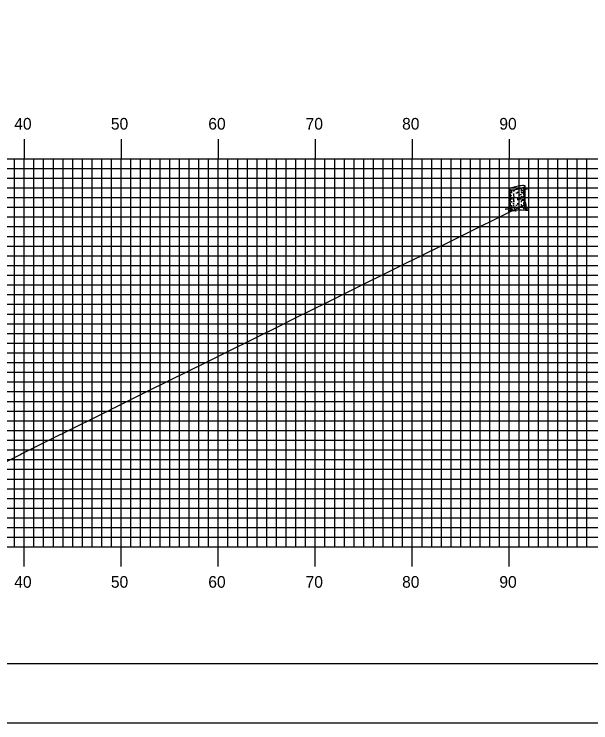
# Model space of a CAD drawing. Extents: x 1684799 to 1685142, y 461260 to 461480.
# Drawn here: x 1685003.7 to 1685063.1, y 461260 to 461333 of the extents above; entities that cross this region are included whole.
import ezdxf

# ---------------------------------------------------------------- set-up
doc = ezdxf.new("R2010")
doc.units = 0
for name, color, linetype in [('BORDER', 7, 'Continuous'), ('H_V ANNOTATION', 7, 'Continuous'), ('M_Trees_Conifer_Pay', 7, 'Continuous'), ('MAJOR', 7, 'Continuous'), ('MINOR', 7, 'Continuous'), ('PLOT BOUNDARY', 7, 'Continuous'), ('S_Roadway_Centerline', 7, 'Continuous')]:
    doc.layers.add(name, color=color, linetype=linetype)

msp = doc.modelspace()

# ---------------------------------------------------------------- linework, layer by layer
at = {"layer": 'BORDER'}
msp.add_lwpolyline([(1684815.116, 461266.072), (1685135.116, 461266.072), (1685135.116, 461476.072), (1684815.116, 461476.072)], close=True, dxfattribs=at)
at = {"layer": 'M_Trees_Conifer_Pay'}
for p, q in [((1685054.699, 461313.193), (1685054.699, 461314.915)), ((1685054.746, 461314.878), (1685054.746, 461314.406)), ((1685054.805, 461314.866), (1685054.805, 461314.769)), ((1685054.93, 461314.858), (1685054.93, 461314.626)), ((1685055.15, 461314.879), (1685055.15, 461314.711)), ((1685055.946, 461314.921), (1685055.946, 461314.721)), ((1685056.174, 461315.117), (1685056.174, 461314.894)), ((1685056.174, 461314.805), (1685056.174, 461314.758)), ((1685056.291, 461315.178), (1685056.291, 461315.015)), ((1685056.291, 461314.948), (1685056.291, 461314.82)), ((1685056.363, 461313.603), (1685056.363, 461315.25)), ((1685054.746, 461314.342), (1685054.746, 461314.034)), ((1685054.805, 461314.694), (1685054.805, 461314.49)), ((1685054.805, 461314.433), (1685054.805, 461314.233)), ((1685054.805, 461314.186), (1685054.805, 461313.85)), ((1685054.93, 461314.586), (1685054.93, 461314.511)), ((1685054.93, 461314.108), (1685054.93, 461313.969)), ((1685055.15, 461314.474), (1685055.15, 461314.237)), ((1685055.555, 461314.647), (1685055.555, 461314.552)), ((1685055.946, 461314.664), (1685055.946, 461314.575)), ((1685055.946, 461314.227), (1685055.946, 461314.122)), ((1685056.174, 461314.423), (1685056.174, 461314.291)), ((1685056.174, 461314.18), (1685056.174, 461314.07)), ((1685056.231, 461314.622), (1685056.18, 461314.563)), ((1685056.291, 461314.633), (1685056.291, 461314.297)), ((1685056.291, 461314.26), (1685056.291, 461314.097)), ((1685054.746, 461313.986), (1685054.746, 461313.494)), ((1685054.746, 461313.441), (1685054.746, 461313.193)), ((1685054.805, 461313.797), (1685054.805, 461313.661)), ((1685054.805, 461313.562), (1685054.805, 461313.183)), ((1685054.93, 461313.698), (1685054.93, 461313.556)), ((1685055.15, 461313.992), (1685055.15, 461313.84)), ((1685055.15, 461313.797), (1685055.15, 461313.624)), ((1685055.15, 461313.346), (1685055.15, 461313.193)), ((1685055.555, 461314.034), (1685055.555, 461313.96)), ((1685055.555, 461313.935), (1685055.555, 461313.786)), ((1685055.555, 461313.494), (1685055.555, 461313.341)), ((1685055.946, 461313.755), (1685055.946, 461313.609)), ((1685055.946, 461313.377), (1685055.946, 461313.288)), ((1685056.174, 461313.935), (1685056.174, 461313.793)), ((1685056.174, 461313.566), (1685056.174, 461313.393)), ((1685056.291, 461314.05), (1685056.291, 461313.834)), ((1685056.291, 461313.803), (1685056.291, 461313.729)), ((1685056.291, 461313.688), (1685056.291, 461313.515)), ((1685054.93, 461313.294), (1685054.93, 461313.2)), ((1685054.93, 461312.8), (1685055.093, 461312.864)), ((1685055.367, 461312.736), (1685055.241, 461312.8))]:
    msp.add_line(p, q, dxfattribs=at)
for points in [[(1685056.18, 461314.748), (1685056.217, 461314.674), (1685056.264, 461314.731), (1685056.322, 461314.799), (1685056.414, 461314.993), (1685056.478, 461315.04), (1685056.509, 461315.047)], [(1685056.194, 461314.495), (1685056.231, 461314.622), (1685056.295, 461314.738), (1685056.326, 461314.805), (1685056.394, 461314.952)], [(1685056.409, 461314.981), (1685056.484, 461314.989), (1685056.556, 461314.89)], [(1685054.878, 461314.221), (1685054.872, 461314.316), (1685054.915, 461314.293), (1685054.915, 461314.198)], [(1685056.146, 461314.711), (1685056.116, 461314.626), (1685056.112, 461314.559), (1685056.142, 461314.495)], [(1685056.363, 461313.603), (1685056.414, 461313.341), (1685056.43, 461313.068), (1685056.488, 461312.942), (1685056.624, 461312.912), (1685056.394, 461312.874), (1685056.394, 461312.874), (1685056.4, 461312.827), (1685056.647, 461312.733), (1685056.373, 461312.749), (1685056.017, 461312.769), (1685055.696, 461312.759), (1685055.702, 461312.841), (1685055.554, 461312.759), (1685055.367, 461312.736), (1685055.391, 461312.668), (1685055.123, 461312.712), (1685054.903, 461312.685), (1685054.61, 461312.702), (1685054.899, 461312.759), (1685054.93, 461312.8), (1685054.767, 461312.858), (1685054.53, 461312.868), (1685054.289, 461312.868), (1685054.631, 461312.926), (1685054.673, 461313.006), (1685054.699, 461313.193)], [(1685056.017, 461313.822), (1685056.03, 461313.745), (1685056.077, 461313.755), (1685056.064, 461313.922)], [(1685056.289, 461313.461), (1685056.295, 461313.315), (1685056.342, 461313.247), (1685056.352, 461313.047)], [(1685054.747, 461313.146), (1685054.726, 461313.068), (1685054.705, 461312.973)], [(1685054.825, 461313.126), (1685054.831, 461313.01), (1685054.778, 461312.921), (1685054.767, 461312.858)], [(1685054.988, 461313.152), (1685054.988, 461313.021), (1685054.899, 461312.921)], [(1685055.214, 461312.912), (1685055.282, 461313.006), (1685055.308, 461313.146)], [(1685055.702, 461312.841), (1685055.776, 461312.983), (1685055.786, 461313.084)], [(1685055.953, 461313.21), (1685055.963, 461313.084), (1685056.037, 461313.041)], [(1685056.231, 461312.821), (1685056.217, 461312.959), (1685056.142, 461313.088)], [(1685056.19, 461313.315), (1685056.264, 461313.21), (1685056.268, 461313.037), (1685056.394, 461312.874)]]:
    msp.add_lwpolyline(points, dxfattribs=at)
for centre, radius, start, end in [((1685054.73, 461314.914), 0.0314, 156.51582, 169.2194), ((1685054.725, 461314.915), 0.0264, 169.2194, 180.03145), ((1685054.722, 461314.915), 0.0226, 180.03145, 191.7194), ((1685054.722, 461314.915), 0.0226, 191.7194, 203.40735), ((1685054.75, 461314.905), 0.0527, 146.7194, 156.51582), ((1685054.725, 461314.916), 0.0264, 203.40735, 214.2194), ((1685054.729, 461314.919), 0.0314, 214.2194, 226.92298), ((1685054.774, 461314.889), 0.0817, 132.38868, 146.7194), ((1685054.744, 461314.935), 0.0527, 226.92298, 236.7194), ((1685054.76, 461314.959), 0.0817, 236.7194, 251.05013), ((1685054.888, 461314.765), 0.251, 124.2194, 132.38868), ((1685054.815, 461315.118), 0.251, 251.05013, 259.2194), ((1685055.198, 461314.309), 0.802, 108.05939, 124.2194), ((1685054.918, 461315.66), 0.802, 259.2194, 275.37941), ((1685056.555, 461310.147), 5.179, 101.7194, 108.05939), ((1685054.507, 461320.018), 5.179, 275.37941, 281.7194), ((1685055.531, 461318.927), 4.124, 264.6955, 266.73309), ((1685056.555, 461310.147), 5.179, 95.37941, 101.7194), ((1685054.507, 461320.018), 5.179, 281.7194, 288.05939), ((1685055.531, 461318.927), 4.124, 276.23804, 278.1032), ((1685056.144, 461314.505), 0.802, 79.2194, 95.37941), ((1685056.032, 461315.409), 0.571, 278.1032, 284.36665), ((1685055.864, 461315.856), 0.802, 288.05939, 304.2194), ((1685056.032, 461315.564), 0.571, 284.43166, 292.41325), ((1685056.032, 461315.409), 0.571, 297.0237, 300), ((1685056.247, 461315.047), 0.251, 71.05013, 79.2194), ((1685056.174, 461315.4), 0.251, 304.2194, 312.38868), ((1685056.231, 461315.219), 0.172, 300, 311.25059), ((1685056.231, 461315.064), 0.172, 300, 311.25059), ((1685056.302, 461315.206), 0.0817, 56.7194, 71.05013), ((1685056.288, 461315.276), 0.0817, 312.38868, 326.7194), ((1685056.304, 461315.136), 0.0624, 311.25059, 330), ((1685056.304, 461314.982), 0.0624, 311.25059, 330), ((1685056.318, 461315.231), 0.0527, 46.92298, 56.7194), ((1685056.333, 461315.246), 0.0314, 34.2194, 46.92298), ((1685056.312, 461315.26), 0.0527, 326.7194, 336.51582), ((1685056.319, 461315.127), 0.0441, 330, 343.94846), ((1685056.319, 461314.973), 0.0441, 330, 343.94846), ((1685056.337, 461315.249), 0.0264, 23.40735, 34.2194), ((1685056.332, 461315.251), 0.0314, 336.51582, 349.2194), ((1685056.34, 461315.25), 0.0226, 11.7194, 23.40735), ((1685056.33, 461315.124), 0.0334, 343.94846, 354.21506), ((1685056.33, 461314.97), 0.0334, 343.94846, 354.21506), ((1685056.34, 461315.25), 0.0226, 0.03145, 11.7194), ((1685056.337, 461315.25), 0.0264, 349.2194, 0.03145), ((1685054.731, 461314.737), 0.0334, 163.94846, 180), ((1685054.731, 461314.737), 0.0334, 180, 196.05154), ((1685054.731, 461314.29), 0.0334, 163.94846, 180), ((1685054.731, 461314.29), 0.0334, 180, 196.05154), ((1685054.731, 461314.08), 0.0334, 163.94846, 180), ((1685054.731, 461314.08), 0.0334, 180, 196.05154), ((1685054.741, 461314.74), 0.0441, 196.05154, 210), ((1685054.741, 461314.293), 0.0441, 196.05154, 210), ((1685054.757, 461314.749), 0.0624, 210, 228.74941), ((1685054.757, 461314.302), 0.0624, 210, 228.74941), ((1685054.83, 461314.831), 0.172, 228.74941, 240), ((1685054.83, 461314.385), 0.172, 228.74941, 240), ((1685055.029, 461315.176), 0.571, 240, 240.33672), ((1685055.029, 461314.73), 0.571, 240, 240.33672), ((1685055.03, 461314.965), 0.571, 240, 247.05866), ((1685055.029, 461315.176), 0.571, 246.85973, 257.98457), ((1685055.53, 461318.247), 4.124, 264.08098, 266.66759), ((1685055.53, 461318.694), 4.124, 268.07512, 270), ((1685055.53, 461318.694), 4.124, 270, 270.35814), ((1685055.531, 461318.483), 4.124, 273.70524, 275.95043), ((1685055.53, 461318.694), 4.124, 275.78493, 277.05584), ((1685055.53, 461318.247), 4.124, 277.61247, 278.1032), ((1685056.031, 461314.73), 0.571, 278.1032, 286.92962), ((1685056.032, 461314.965), 0.571, 284.44928, 297.04285), ((1685056.031, 461314.73), 0.571, 297.18959, 300), ((1685056.23, 461314.385), 0.172, 300, 311.25059), ((1685056.302, 461314.302), 0.0624, 311.25059, 330), ((1685056.318, 461314.293), 0.0441, 330, 343.94846), ((1685056.328, 461314.29), 0.0334, 343.94846, 354.21506), ((1685056.328, 461314.08), 0.0334, 343.94846, 354.21506), ((1685056.33, 461314.526), 0.0334, 343.94846, 354.21506), ((1685054.731, 461313.843), 0.0334, 163.94846, 180), ((1685054.731, 461313.843), 0.0334, 180, 196.05154), ((1685054.731, 461313.645), 0.0334, 163.94846, 180), ((1685054.731, 461313.45), 0.0334, 163.94846, 180), ((1685054.731, 461313.45), 0.0334, 180, 196.05154), ((1685054.741, 461314.083), 0.0441, 196.05154, 210), ((1685054.741, 461313.846), 0.0441, 196.05154, 210), ((1685054.741, 461313.453), 0.0441, 196.05154, 210), ((1685054.757, 461314.092), 0.0624, 210, 228.74941), ((1685054.757, 461313.855), 0.0624, 210, 228.74941), ((1685054.757, 461313.462), 0.0624, 210, 228.74941), ((1685054.83, 461314.175), 0.172, 228.74941, 240), ((1685054.83, 461313.938), 0.172, 228.74941, 240), ((1685054.83, 461313.545), 0.172, 228.74941, 240), ((1685055.029, 461314.52), 0.571, 240, 246.85973), ((1685055.029, 461314.283), 0.571, 240, 246.85973), ((1685055.018, 461314.091), 0.571, 241.23686, 248.02677), ((1685055.029, 461313.89), 0.571, 240, 246.85973), ((1685055.029, 461314.52), 0.571, 259.27072, 261.8968), ((1685055.53, 461318.037), 4.124, 261.8968, 263.14738), ((1685055.53, 461317.603), 4.124, 263.49906, 265.83975), ((1685055.53, 461317.8), 4.124, 264.71603, 266.31934), ((1685055.53, 461318.037), 4.124, 270, 270.35814), ((1685055.53, 461318.037), 4.124, 273.14934, 275.45691), ((1685056.031, 461314.283), 0.571, 285.39827, 297.18959), ((1685056.031, 461313.89), 0.571, 288.50673, 297.27208), ((1685056.031, 461314.085), 0.571, 289.29072, 300), ((1685056.031, 461314.52), 0.571, 297.18959, 300), ((1685056.23, 461314.175), 0.172, 300, 311.25059), ((1685056.23, 461313.74), 0.172, 300, 311.25059), ((1685056.302, 461314.092), 0.0624, 311.25059, 330), ((1685056.302, 461313.658), 0.0624, 311.25059, 330), ((1685056.318, 461314.083), 0.0441, 330, 343.94846), ((1685056.318, 461313.648), 0.0441, 330, 343.94846), ((1685056.328, 461313.645), 0.0334, 343.94846, 354.21506), ((1685054.731, 461313.229), 0.0334, 163.94846, 180), ((1685054.731, 461313.229), 0.0334, 180, 196.05154), ((1685054.741, 461313.232), 0.0441, 196.05154, 210), ((1685054.757, 461313.242), 0.0624, 210, 228.74941), ((1685054.83, 461313.324), 0.172, 228.74941, 240), ((1685055.029, 461313.669), 0.571, 240, 244.53138), ((1685055.53, 461317.187), 4.124, 262.44379, 263.51202), ((1685055.53, 461317.407), 4.124, 267.81166, 270), ((1685055.53, 461317.407), 4.124, 270, 270.13279), ((1685055.53, 461317.407), 4.124, 275.78493, 276.78961), ((1685055.53, 461317.187), 4.124, 277.36842, 278.1032), ((1685056.031, 461313.669), 0.571, 278.1032, 281.63703), ((1685056.23, 461313.324), 0.172, 300, 311.25059), ((1685056.302, 461313.242), 0.0624, 311.25059, 330), ((1685056.318, 461313.232), 0.0441, 330, 343.94846), ((1685056.328, 461313.229), 0.0334, 343.94846, 354.21506)]:
    msp.add_arc(centre, radius, start, end, dxfattribs=at)
at = {"layer": 'MAJOR'}
for p, q in [((1685004.716, 461320.076), (1685004.716, 461318.072)), ((1685014.716, 461320.076), (1685014.716, 461318.072)), ((1685024.716, 461320.076), (1685024.716, 461318.072)), ((1685034.716, 461320.076), (1685034.716, 461318.072)), ((1685044.716, 461320.076), (1685044.716, 461318.072)), ((1685054.716, 461320.076), (1685054.716, 461318.072)), ((1684824.716, 461318.072), (1685104.716, 461318.072)), ((1684824.716, 461318.072), (1685104.716, 461318.072)), ((1685004.716, 461278.072), (1685004.716, 461318.072)), ((1685014.716, 461278.072), (1685014.716, 461318.072)), ((1685024.716, 461278.072), (1685024.716, 461318.072)), ((1685034.716, 461278.072), (1685034.716, 461318.072)), ((1685044.716, 461278.072), (1685044.716, 461318.072)), ((1685054.716, 461278.072), (1685054.716, 461318.072)), ((1684824.716, 461313.072), (1685104.716, 461313.072)), ((1684824.716, 461308.072), (1685104.716, 461308.072)), ((1684824.716, 461303.072), (1685104.716, 461303.072)), ((1684824.716, 461298.072), (1685104.716, 461298.072)), ((1684824.716, 461293.072), (1685104.716, 461293.072)), ((1684824.716, 461288.072), (1685104.716, 461288.072)), ((1684824.716, 461283.072), (1685104.716, 461283.072)), ((1684824.716, 461278.072), (1685104.716, 461278.072)), ((1684824.716, 461278.072), (1685104.716, 461278.072)), ((1685004.716, 461276.068), (1685004.716, 461278.072)), ((1685014.716, 461276.068), (1685014.716, 461278.072)), ((1685024.716, 461276.068), (1685024.716, 461278.072)), ((1685034.716, 461276.068), (1685034.716, 461278.072)), ((1685044.716, 461276.068), (1685044.716, 461278.072)), ((1685054.716, 461276.068), (1685054.716, 461278.072))]:
    msp.add_line(p, q, dxfattribs=at)
at = {"layer": 'MINOR'}
for p, q in [((1685003.716, 461278.072), (1685003.716, 461318.072)), ((1685005.716, 461278.072), (1685005.716, 461318.072)), ((1685006.716, 461278.072), (1685006.716, 461318.072)), ((1685007.716, 461278.072), (1685007.716, 461318.072)), ((1685008.716, 461278.072), (1685008.716, 461318.072)), ((1685009.716, 461278.072), (1685009.716, 461318.072)), ((1685010.716, 461278.072), (1685010.716, 461318.072)), ((1685011.716, 461278.072), (1685011.716, 461318.072)), ((1685012.716, 461278.072), (1685012.716, 461318.072)), ((1685013.716, 461278.072), (1685013.716, 461318.072)), ((1685015.716, 461278.072), (1685015.716, 461318.072)), ((1685016.716, 461278.072), (1685016.716, 461318.072)), ((1685017.716, 461278.072), (1685017.716, 461318.072)), ((1685018.716, 461278.072), (1685018.716, 461318.072)), ((1685019.716, 461278.072), (1685019.716, 461318.072)), ((1685020.716, 461278.072), (1685020.716, 461318.072)), ((1685021.716, 461278.072), (1685021.716, 461318.072)), ((1685022.716, 461278.072), (1685022.716, 461318.072)), ((1685023.716, 461278.072), (1685023.716, 461318.072)), ((1685025.716, 461278.072), (1685025.716, 461318.072)), ((1685026.716, 461278.072), (1685026.716, 461318.072)), ((1685027.716, 461278.072), (1685027.716, 461318.072)), ((1685028.716, 461278.072), (1685028.716, 461318.072)), ((1685029.716, 461278.072), (1685029.716, 461318.072)), ((1685030.716, 461278.072), (1685030.716, 461318.072)), ((1685031.716, 461278.072), (1685031.716, 461318.072)), ((1685032.716, 461278.072), (1685032.716, 461318.072)), ((1685033.716, 461278.072), (1685033.716, 461318.072)), ((1685035.716, 461278.072), (1685035.716, 461318.072)), ((1685036.716, 461278.072), (1685036.716, 461318.072)), ((1685037.716, 461278.072), (1685037.716, 461318.072)), ((1685038.716, 461278.072), (1685038.716, 461318.072)), ((1685039.716, 461278.072), (1685039.716, 461318.072)), ((1685040.716, 461278.072), (1685040.716, 461318.072)), ((1685041.716, 461278.072), (1685041.716, 461318.072)), ((1685042.716, 461278.072), (1685042.716, 461318.072)), ((1685043.716, 461278.072), (1685043.716, 461318.072)), ((1685045.716, 461278.072), (1685045.716, 461318.072)), ((1685046.716, 461278.072), (1685046.716, 461318.072)), ((1685047.716, 461278.072), (1685047.716, 461318.072)), ((1685048.716, 461278.072), (1685048.716, 461318.072)), ((1685049.716, 461278.072), (1685049.716, 461318.072)), ((1685050.716, 461278.072), (1685050.716, 461318.072)), ((1685051.716, 461278.072), (1685051.716, 461318.072)), ((1685052.716, 461278.072), (1685052.716, 461318.072)), ((1685053.716, 461278.072), (1685053.716, 461318.072)), ((1685055.716, 461278.072), (1685055.716, 461318.072)), ((1685056.716, 461278.072), (1685056.716, 461318.072)), ((1685057.716, 461278.072), (1685057.716, 461318.072)), ((1685058.716, 461278.072), (1685058.716, 461318.072)), ((1685059.716, 461278.072), (1685059.716, 461318.072)), ((1685060.716, 461278.072), (1685060.716, 461318.072)), ((1685061.716, 461278.072), (1685061.716, 461318.072)), ((1685062.716, 461278.072), (1685062.716, 461318.072)), ((1684824.716, 461317.072), (1685104.716, 461317.072)), ((1684824.716, 461316.072), (1685104.716, 461316.072)), ((1684824.716, 461315.072), (1685104.716, 461315.072)), ((1684824.716, 461314.072), (1685104.716, 461314.072)), ((1684824.716, 461312.072), (1685104.716, 461312.072)), ((1684824.716, 461311.072), (1685104.716, 461311.072)), ((1684824.716, 461310.072), (1685104.716, 461310.072)), ((1684824.716, 461309.072), (1685104.716, 461309.072)), ((1684824.716, 461307.072), (1685104.716, 461307.072)), ((1684824.716, 461306.072), (1685104.716, 461306.072)), ((1684824.716, 461305.072), (1685104.716, 461305.072)), ((1684824.716, 461304.072), (1685104.716, 461304.072)), ((1684824.716, 461302.072), (1685104.716, 461302.072)), ((1684824.716, 461301.072), (1685104.716, 461301.072)), ((1684824.716, 461300.072), (1685104.716, 461300.072)), ((1684824.716, 461299.072), (1685104.716, 461299.072)), ((1684824.716, 461297.072), (1685104.716, 461297.072)), ((1684824.716, 461296.072), (1685104.716, 461296.072)), ((1684824.716, 461295.072), (1685104.716, 461295.072)), ((1684824.716, 461294.072), (1685104.716, 461294.072)), ((1684824.716, 461292.072), (1685104.716, 461292.072)), ((1684824.716, 461291.072), (1685104.716, 461291.072)), ((1684824.716, 461290.072), (1685104.716, 461290.072)), ((1684824.716, 461289.072), (1685104.716, 461289.072)), ((1684824.716, 461287.072), (1685104.716, 461287.072)), ((1684824.716, 461286.072), (1685104.716, 461286.072)), ((1684824.716, 461285.072), (1685104.716, 461285.072)), ((1684824.716, 461284.072), (1685104.716, 461284.072)), ((1684824.716, 461282.072), (1685104.716, 461282.072)), ((1684824.716, 461281.072), (1685104.716, 461281.072)), ((1684824.716, 461280.072), (1685104.716, 461280.072)), ((1684824.716, 461279.072), (1685104.716, 461279.072))]:
    msp.add_line(p, q, dxfattribs=at)
at = {"layer": 'PLOT BOUNDARY'}
msp.add_lwpolyline([(1684798.93, 461259.954), (1685138.93, 461259.954), (1685138.93, 461479.954), (1684798.93, 461479.954)], close=True, dxfattribs=at)
at = {"layer": 'S_Roadway_Centerline'}
msp.add_lwpolyline([(1685000.197, 461285.571), (1685004.25, 461287.58), (1685004.468, 461287.688), (1685004.694, 461287.8), (1685008.432, 461289.653), (1685008.614, 461289.743), (1685008.676, 461289.773), (1685008.801, 461289.835), (1685008.993, 461289.93), (1685012.87, 461291.852), (1685013.536, 461292.182), (1685013.69, 461292.258), (1685014.176, 461292.499), (1685017.986, 461294.387), (1685018.188, 461294.487), (1685018.828, 461294.804), (1685022.434, 461296.591), (1685022.686, 461296.715), (1685023.486, 461297.112), (1685026.881, 461298.794), (1685027.185, 461298.944), (1685028.15, 461299.423), (1685031.326, 461300.997), (1685031.683, 461301.173), (1685032.051, 461301.355), (1685032.545, 461301.599), (1685036.028, 461303.325), (1685036.586, 461303.601), (1685039.901, 461305.244), (1685040.508, 461305.544), (1685041.169, 461305.871), (1685044.131, 461307.338), (1685044.911, 461307.725), (1685045.758, 461308.143), (1685046.064, 461308.293), (1685048.41, 461309.456), (1685049.504, 461309.998), (1685050.06, 461310.271), (1685051.1, 461310.781), (1685053.734, 461312.085), (1685056.191, 461313.277), (1685056.209, 461313.276), (1685056.327, 461313.268), (1685056.466, 461313.259)], dxfattribs=at)

# ---------------------------------------------------------------- texts
at = {"layer": 'H_V ANNOTATION'}
for s, p in [('40', (1685003.689, 461321.072)), ('50', (1685013.646, 461321.072)), ('60', (1685023.689, 461321.072)), ('70', (1685033.72, 461321.072)), ('80', (1685043.667, 461321.072)), ('90', (1685053.689, 461321.072)), ('40', (1685003.689, 461273.872)), ('50', (1685013.646, 461273.872)), ('60', (1685023.689, 461273.872)), ('70', (1685033.72, 461273.872)), ('80', (1685043.667, 461273.872)), ('90', (1685053.689, 461273.872))]:
    msp.add_text(s, height=1.2, dxfattribs=at).set_placement(p)

doc.saveas('drawing.dxf')
